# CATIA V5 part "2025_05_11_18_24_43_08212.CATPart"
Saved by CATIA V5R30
Part number: 2025_05_11_18_24_43_08212
Definition: 2025_05_11_18_24_43_0821
Nomenclature: 2025_05_11_18_24_43_0821
Source: Unknown
Description: PART-2025_05_11_18_24_43_0821-DESC
Bounding box of the stored display mesh (mm): x 240.75 to 266.25, y -12.75 to 12.75, z 0 to 53
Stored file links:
  E:\Bakalarka\Model\Forma_v7\2025_05_11_18_24_43_08212.CATPart
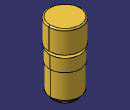
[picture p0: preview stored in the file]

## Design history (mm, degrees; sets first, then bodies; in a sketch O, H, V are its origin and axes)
Body1 "MANIFOLD_SOLID_BREP #148" (main body)
  Solid1: solid without history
